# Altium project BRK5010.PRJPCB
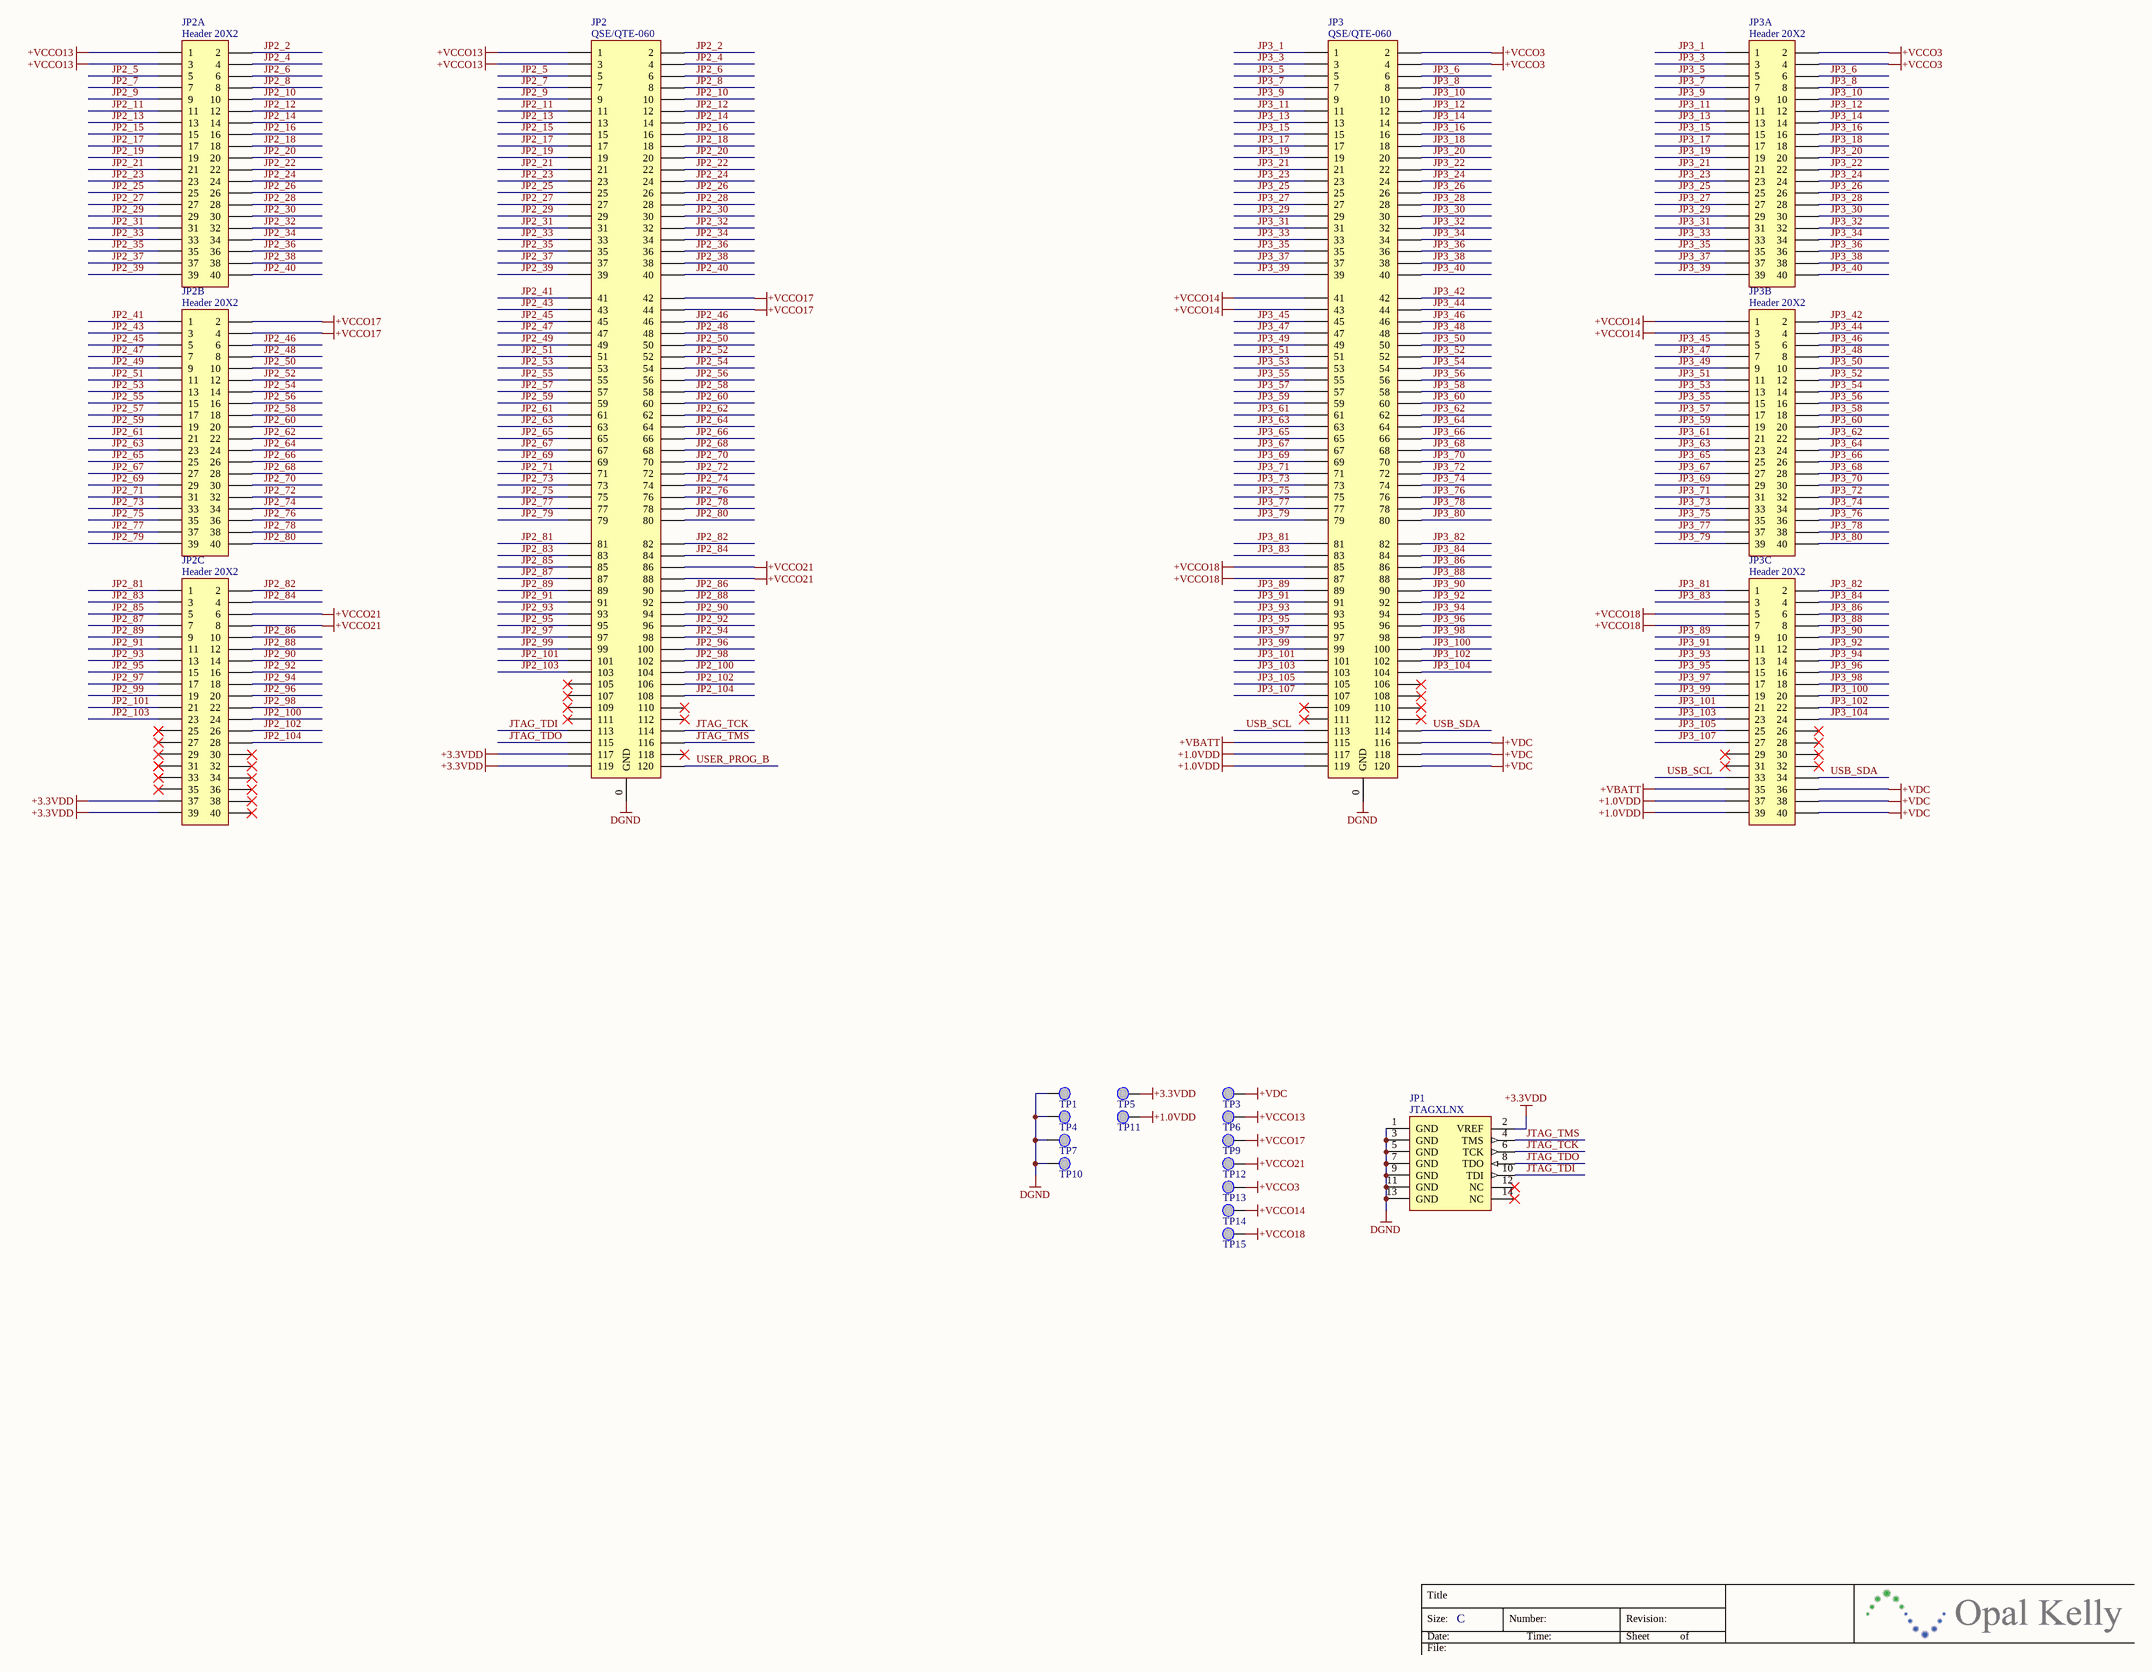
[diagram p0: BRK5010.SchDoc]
1 sheet, 22 parts. Net scope: global (net labels, ports and power ports of the same name join across sheets).
Board file: BRK5010.PcbDoc

## Sheet BRK5010.SchDoc: BRK5010
size C; Author: Jake Janovetz; Organization: Opal Kelly; Address1: 13500 SW 72nd Ave, STE 120; Address2: Portland, OR 97223; Address3: 217.391.3724; Address4: http://www.opalkelly.com; DocumentNumber: xxx; Revision: 1; SheetNumber: 1; SheetTotal: 1; PageSetup: Record=PageOptions|CenterHorizontal=True|CenterVertical=True|PrintScale=0.54|XCorrection=1.00|YCorrection=1.00|PrintKind=0|BorderSize=5000000|LeftOffset=0|BottomOffset=0|Orientation=2|PaperLength=1000|PaperWidth=1000|Scale=100|PaperSource=7|PrintQuality=-4|MediaType=1|DitherType=10|PaperKind=Letter|PrintScaleMode=1

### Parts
JP1  JTAGXLNX  [HDR2X7-2MM]
JP2  QSE/QTE-060  [QTE-060-01-X-D]
JP2A  Header 20X2  [HDR2X20-2MM]
JP2B  Header 20X2  [HDR2X20-2MM]
JP2C  Header 20X2  [HDR2X20-2MM]
JP3  QSE/QTE-060  [QTE-060-01-X-D]
JP3A  Header 20X2  [HDR2X20-2MM]
JP3B  Header 20X2  [HDR2X20-2MM]
JP3C  Header 20X2  [HDR2X20-2MM]
TP1  TESTPOINT  [TP_MED]  (value not drawn)
TP3  TESTPOINT  [TP_MED]  (value not drawn)
TP4  TESTPOINT  [TP_MED]  (value not drawn)
TP5  TESTPOINT  [TP_MED]  (value not drawn)
TP6  TESTPOINT  [TP_MED]  (value not drawn)
TP7  TESTPOINT  [TP_MED]  (value not drawn)
TP9  TESTPOINT  [TP_MED]  (value not drawn)
TP10  TESTPOINT  [TP_MED]  (value not drawn)
TP11  TESTPOINT  [TP_MED]  (value not drawn)
TP12  TESTPOINT  [TP_MED]  (value not drawn)
TP13  TESTPOINT  [TP_MED]  (value not drawn)
TP14  TESTPOINT  [TP_MED]  (value not drawn)
TP15  TESTPOINT  [TP_MED]  (value not drawn)

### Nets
+1.0VDD: JP3.117 JP3.119 JP3C.37 JP3C.39 TP11.1(PIN)
+3.3VDD: JP1.2(VREF) JP2.117 JP2.119 JP2C.37 JP2C.39 TP5.1(PIN)
+VBATT: JP3.115 JP3C.35
+VCCO3: JP3.2 JP3.4 JP3A.2 JP3A.4 TP13.1(PIN)
+VCCO13: JP2.1 JP2.3 JP2A.1 JP2A.3 TP6.1(PIN)
+VCCO14: JP3.41 JP3.43 JP3B.1 JP3B.3 TP14.1(PIN)
+VCCO17: JP2.42 JP2.44 JP2B.2 JP2B.4 TP9.1(PIN)
+VCCO18: JP3.85 JP3.87 JP3C.5 JP3C.7 TP15.1(PIN)
+VCCO21: JP2.86 JP2.88 JP2C.6 JP2C.8 TP12.1(PIN)
+VDC: JP3.116 JP3.118 JP3.120 JP3C.36 JP3C.38 JP3C.40 TP3.1(PIN)
DGND: JP1.1(GND) JP1.3(GND) JP1.5(GND) JP1.7(GND) JP1.9(GND) JP1.11(GND) JP1.13(GND) JP2.0(GND) JP3.0(GND) TP1.1(PIN) TP4.1(PIN) TP7.1(PIN) TP10.1(PIN)
JP2_2: JP2.2 JP2A.2
JP2_4: JP2.4 JP2A.4
JP2_5: JP2.5 JP2A.5
JP2_6: JP2.6 JP2A.6
JP2_7: JP2.7 JP2A.7
JP2_8: JP2.8 JP2A.8
JP2_9: JP2.9 JP2A.9
JP2_10: JP2.10 JP2A.10
JP2_11: JP2.11 JP2A.11
JP2_12: JP2.12 JP2A.12
JP2_13: JP2.13 JP2A.13
JP2_14: JP2.14 JP2A.14
JP2_15: JP2.15 JP2A.15
JP2_16: JP2.16 JP2A.16
JP2_17: JP2.17 JP2A.17
JP2_18: JP2.18 JP2A.18
JP2_19: JP2.19 JP2A.19
JP2_20: JP2.20 JP2A.20
JP2_21: JP2.21 JP2A.21
JP2_22: JP2.22 JP2A.22
JP2_23: JP2.23 JP2A.23
JP2_24: JP2.24 JP2A.24
JP2_25: JP2.25 JP2A.25
JP2_26: JP2.26 JP2A.26
JP2_27: JP2.27 JP2A.27
JP2_28: JP2.28 JP2A.28
JP2_29: JP2.29 JP2A.29
JP2_30: JP2.30 JP2A.30
JP2_31: JP2.31 JP2A.31
JP2_32: JP2.32 JP2A.32
JP2_33: JP2.33 JP2A.33
JP2_34: JP2.34 JP2A.34
JP2_35: JP2.35 JP2A.35
JP2_36: JP2.36 JP2A.36
JP2_37: JP2.37 JP2A.37
JP2_38: JP2.38 JP2A.38
JP2_39: JP2.39 JP2A.39
JP2_40: JP2.40 JP2A.40
JP2_41: JP2.41 JP2B.1
JP2_43: JP2.43 JP2B.3
JP2_45: JP2.45 JP2B.5
JP2_46: JP2.46 JP2B.6
JP2_47: JP2.47 JP2B.7
JP2_48: JP2.48 JP2B.8
JP2_49: JP2.49 JP2B.9
JP2_50: JP2.50 JP2B.10
JP2_51: JP2.51 JP2B.11
JP2_52: JP2.52 JP2B.12
JP2_53: JP2.53 JP2B.13
JP2_54: JP2.54 JP2B.14
JP2_55: JP2.55 JP2B.15
JP2_56: JP2.56 JP2B.16
JP2_57: JP2.57 JP2B.17
JP2_58: JP2.58 JP2B.18
JP2_59: JP2.59 JP2B.19
JP2_60: JP2.60 JP2B.20
JP2_61: JP2.61 JP2B.21
JP2_62: JP2.62 JP2B.22
JP2_63: JP2.63 JP2B.23
JP2_64: JP2.64 JP2B.24
JP2_65: JP2.65 JP2B.25
JP2_66: JP2.66 JP2B.26
JP2_67: JP2.67 JP2B.27
JP2_68: JP2.68 JP2B.28
JP2_69: JP2.69 JP2B.29
JP2_70: JP2.70 JP2B.30
JP2_71: JP2.71 JP2B.31
JP2_72: JP2.72 JP2B.32
JP2_73: JP2.73 JP2B.33
JP2_74: JP2.74 JP2B.34
JP2_75: JP2.75 JP2B.35
JP2_76: JP2.76 JP2B.36
JP2_77: JP2.77 JP2B.37
JP2_78: JP2.78 JP2B.38
JP2_79: JP2.79 JP2B.39
JP2_80: JP2.80 JP2B.40
JP2_81: JP2.81 JP2C.1
JP2_82: JP2.82 JP2C.2
JP2_83: JP2.83 JP2C.3
JP2_84: JP2.84 JP2C.4
JP2_85: JP2.85 JP2C.5
JP2_86: JP2.90 JP2C.10
JP2_87: JP2.87 JP2C.7
JP2_88: JP2.92 JP2C.12
JP2_89: JP2.89 JP2C.9
JP2_90: JP2.94 JP2C.14
JP2_91: JP2.91 JP2C.11
JP2_92: JP2.96 JP2C.16
JP2_93: JP2.93 JP2C.13
JP2_94: JP2.98 JP2C.18
JP2_95: JP2.95 JP2C.15
JP2_96: JP2.100 JP2C.20
JP2_97: JP2.97 JP2C.17
JP2_98: JP2.102 JP2C.22
JP2_99: JP2.99 JP2C.19
JP2_100: JP2.104 JP2C.24
JP2_101: JP2.101 JP2C.21
JP2_102: JP2.106 JP2C.26
JP2_103: JP2.103 JP2C.23
JP2_104: JP2.108 JP2C.28
JP3_1: JP3.1 JP3A.1
JP3_3: JP3.3 JP3A.3
JP3_5: JP3.5 JP3A.5
JP3_6: JP3.6 JP3A.6
JP3_7: JP3.7 JP3A.7
JP3_8: JP3.8 JP3A.8
JP3_9: JP3.9 JP3A.9
JP3_10: JP3.10 JP3A.10
JP3_11: JP3.11 JP3A.11
JP3_12: JP3.12 JP3A.12
JP3_13: JP3.13 JP3A.13
JP3_14: JP3.14 JP3A.14
JP3_15: JP3.15 JP3A.15
JP3_16: JP3.16 JP3A.16
JP3_17: JP3.17 JP3A.17
JP3_18: JP3.18 JP3A.18
JP3_19: JP3.19 JP3A.19
JP3_20: JP3.20 JP3A.20
JP3_21: JP3.21 JP3A.21
JP3_22: JP3.22 JP3A.22
JP3_23: JP3.23 JP3A.23
JP3_24: JP3.24 JP3A.24
JP3_25: JP3.25 JP3A.25
JP3_26: JP3.26 JP3A.26
JP3_27: JP3.27 JP3A.27
JP3_28: JP3.28 JP3A.28
JP3_29: JP3.29 JP3A.29
JP3_30: JP3.30 JP3A.30
JP3_31: JP3.31 JP3A.31
JP3_32: JP3.32 JP3A.32
JP3_33: JP3.33 JP3A.33
JP3_34: JP3.34 JP3A.34
JP3_35: JP3.35 JP3A.35
JP3_36: JP3.36 JP3A.36
JP3_37: JP3.37 JP3A.37
JP3_38: JP3.38 JP3A.38
JP3_39: JP3.39 JP3A.39
JP3_40: JP3.40 JP3A.40
JP3_42: JP3.42 JP3B.2
JP3_44: JP3.44 JP3B.4
JP3_45: JP3.45 JP3B.5
JP3_46: JP3.46 JP3B.6
JP3_47: JP3.47 JP3B.7
JP3_48: JP3.48 JP3B.8
JP3_49: JP3.49 JP3B.9
JP3_50: JP3.50 JP3B.10
JP3_51: JP3.51 JP3B.11
JP3_52: JP3.52 JP3B.12
JP3_53: JP3.53 JP3B.13
JP3_54: JP3.54 JP3B.14
JP3_55: JP3.55 JP3B.15
JP3_56: JP3.56 JP3B.16
JP3_57: JP3.57 JP3B.17
JP3_58: JP3.58 JP3B.18
JP3_59: JP3.59 JP3B.19
JP3_60: JP3.60 JP3B.20
JP3_61: JP3.61 JP3B.21
JP3_62: JP3.62 JP3B.22
JP3_63: JP3.63 JP3B.23
JP3_64: JP3.64 JP3B.24
JP3_65: JP3.65 JP3B.25
JP3_66: JP3.66 JP3B.26
JP3_67: JP3.67 JP3B.27
JP3_68: JP3.68 JP3B.28
JP3_69: JP3.69 JP3B.29
JP3_70: JP3.70 JP3B.30
JP3_71: JP3.71 JP3B.31
JP3_72: JP3.72 JP3B.32
JP3_73: JP3.73 JP3B.33
JP3_74: JP3.74 JP3B.34
JP3_75: JP3.75 JP3B.35
JP3_76: JP3.76 JP3B.36
JP3_77: JP3.77 JP3B.37
JP3_78: JP3.78 JP3B.38
JP3_79: JP3.79 JP3B.39
JP3_80: JP3.80 JP3B.40
JP3_81: JP3.81 JP3C.1
JP3_82: JP3.82 JP3C.2
JP3_83: JP3.83 JP3C.3
JP3_84: JP3.84 JP3C.4
JP3_86: JP3.86 JP3C.6
JP3_88: JP3.88 JP3C.8
JP3_89: JP3.89 JP3C.9
JP3_90: JP3.90 JP3C.10
JP3_91: JP3.91 JP3C.11
JP3_92: JP3.92 JP3C.12
JP3_93: JP3.93 JP3C.13
JP3_94: JP3.94 JP3C.14
JP3_95: JP3.95 JP3C.15
JP3_96: JP3.96 JP3C.16
JP3_97: JP3.97 JP3C.17
JP3_98: JP3.98 JP3C.18
JP3_99: JP3.99 JP3C.19
JP3_100: JP3.100 JP3C.20
JP3_101: JP3.101 JP3C.21
JP3_102: JP3.102 JP3C.22
JP3_103: JP3.103 JP3C.23
JP3_104: JP3.104 JP3C.24
JP3_105: JP3.105 JP3C.25
JP3_107: JP3.107 JP3C.27
JTAG_TCK: JP1.6(TCK) JP2.114
JTAG_TDI: JP1.10(TDI) JP2.113
JTAG_TDO: JP1.8(TDO) JP2.115
JTAG_TMS: JP1.4(TMS) JP2.116
USB_SCL: JP3.113 JP3C.33
USB_SDA: JP3.114 JP3C.34
USER_PROG_B: JP2.120

Not connected (* = marked no-connect by the designer): JP1 12(NC)* 14(NC)*; JP2 105* 107* 109* 110* 111* 112* 118*; JP2C 25* 27* 29* 30* 31* 32* 33* 34* 35* 36* 38* 40*; JP3 106* 108* 109* 110* 111* 112*; JP3C 26* 28* 29* 30* 31* 32*

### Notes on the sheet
- Title
- Size:
- Date:
- File:
- C
- Number:
- Time:
- Revision:
- Sheet
- of

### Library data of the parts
JP1 = JTAGXLNX: Xilinx JTAG Header, 7-Pin, Dual row; Manufacturer: Generic Components; Class I: Connector
JP2 JP3 = QSE/QTE-060: Header/Socket - 120-pin - Edge mount, .80mm; PartNumber: 000497
JP2A JP2B JP2C JP3A JP3B JP3C = Header 20X2: Header, 20-Pin, Dual row; Manufacturer: Generic Components; Class I: Connector
TP1 TP3-TP7 TP9-TP15 = TESTPOINT: PartNumber: 000042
